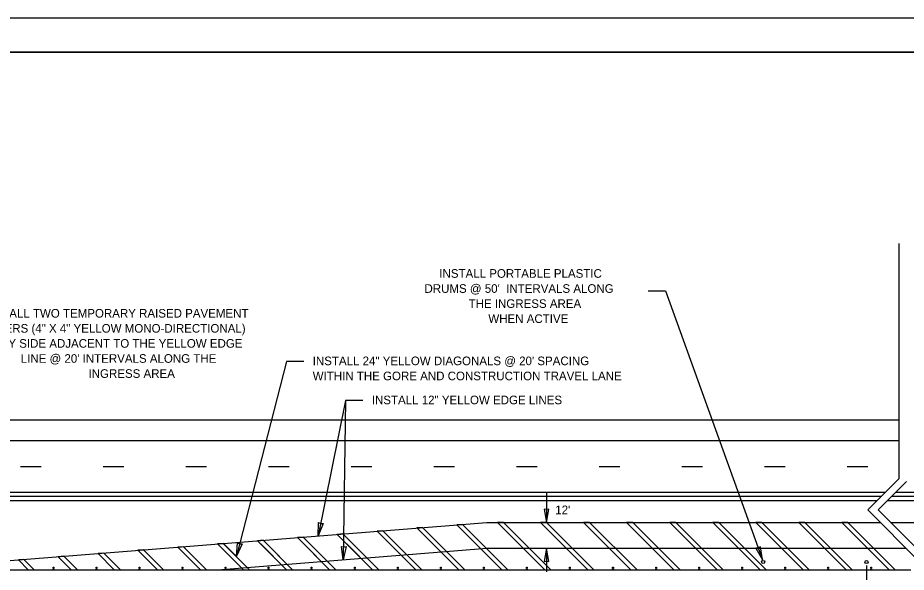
# Model space of a CAD drawing. Extents: x -2541 to -1265, y -5743 to -4928.
# Drawn here: x -2108.9 to -1696.1, y -5185.3 to -4927.7 of the extents above; entities that cross this region are included whole.
import ezdxf

# ---------------------------------------------------------------- set-up
doc = ezdxf.new("R2010")
doc.units = 0
for name, color, linetype in [('Level 42', 7, 'Continuous'), ('Level 45', 7, 'Continuous'), ('Level 46', 7, 'Continuous'), ('Level 48', 7, 'Continuous'), ('Level 49', 7, 'Continuous'), ('Level 50', 7, 'Continuous'), ('TR_WZ_TC_Edge Lines', 7, 'Continuous')]:
    doc.layers.add(name, color=color, linetype=linetype)

msp = doc.modelspace()

# ---------------------------------------------------------------- linework, layer by layer
at = {"layer": 'Level 42'}
for p, q in [((-1278.76, -4943.69), (-2472.96, -4943.66)), ((-1863.17, -5147.99), (-1863.17, -5162.16)), ((-1863.17, -5174.16), (-1863.17, -5185.16))]:
    msp.add_line(p, q, dxfattribs=at)
msp.add_lwpolyline([(-2472.96, -4943.66), (-1412.92, -4943.66), (-1412.92, -5724.9), (-2472.96, -5724.9)], close=True, dxfattribs=at)
at = {"layer": 'Level 45'}
for p, q in [((-2451.65, -5148.16), (-1705.85, -5148.16)), ((-1701.04, -5148.16), (-1460.65, -5148.16)), ((-2451.65, -5184.16), (-1693.96, -5184.16)), ((-2092.51, -5183.2), (-2092.51, -5182.88)), ((-2092.51, -5182.88), (-2092.19, -5182.88)), ((-2092.19, -5183.2), (-2092.51, -5183.2)), ((-2092.51, -5183.84), (-2092.51, -5183.52)), ((-2092.51, -5183.52), (-2092.19, -5183.52)), ((-2092.19, -5183.84), (-2092.51, -5183.84)), ((-2092.19, -5182.88), (-2092.19, -5183.2)), ((-2092.19, -5183.52), (-2092.19, -5183.84)), ((-2072.51, -5183.2), (-2072.51, -5182.88)), ((-2072.51, -5182.88), (-2072.19, -5182.88)), ((-2072.19, -5183.2), (-2072.51, -5183.2)), ((-2072.51, -5183.84), (-2072.51, -5183.52)), ((-2072.51, -5183.52), (-2072.19, -5183.52)), ((-2072.19, -5183.84), (-2072.51, -5183.84)), ((-2072.19, -5182.88), (-2072.19, -5183.2)), ((-2072.19, -5183.52), (-2072.19, -5183.84)), ((-2052.51, -5183.2), (-2052.51, -5182.88)), ((-2052.51, -5182.88), (-2052.19, -5182.88)), ((-2052.19, -5183.2), (-2052.51, -5183.2)), ((-2052.51, -5183.84), (-2052.51, -5183.52)), ((-2052.51, -5183.52), (-2052.19, -5183.52)), ((-2052.19, -5183.84), (-2052.51, -5183.84)), ((-2052.19, -5182.88), (-2052.19, -5183.2)), ((-2052.19, -5183.52), (-2052.19, -5183.84)), ((-2032.51, -5183.2), (-2032.51, -5182.88)), ((-2032.51, -5182.88), (-2032.19, -5182.88)), ((-2032.19, -5183.2), (-2032.51, -5183.2)), ((-2032.51, -5183.84), (-2032.51, -5183.52)), ((-2032.51, -5183.52), (-2032.19, -5183.52)), ((-2032.19, -5183.84), (-2032.51, -5183.84)), ((-2032.19, -5182.88), (-2032.19, -5183.2)), ((-2032.19, -5183.52), (-2032.19, -5183.84)), ((-2012.51, -5183.2), (-2012.51, -5182.88)), ((-2012.51, -5182.88), (-2012.19, -5182.88)), ((-2012.19, -5183.2), (-2012.51, -5183.2)), ((-2012.51, -5183.84), (-2012.51, -5183.52)), ((-2012.51, -5183.52), (-2012.19, -5183.52)), ((-2012.19, -5183.84), (-2012.51, -5183.84)), ((-2012.19, -5182.88), (-2012.19, -5183.2)), ((-2012.19, -5183.52), (-2012.19, -5183.84)), ((-1992.51, -5183.2), (-1992.51, -5182.88)), ((-1992.51, -5182.88), (-1992.19, -5182.88)), ((-1992.19, -5183.2), (-1992.51, -5183.2)), ((-1992.51, -5183.84), (-1992.51, -5183.52)), ((-1992.51, -5183.52), (-1992.19, -5183.52)), ((-1992.19, -5183.84), (-1992.51, -5183.84)), ((-1992.19, -5182.88), (-1992.19, -5183.2)), ((-1992.19, -5183.52), (-1992.19, -5183.84)), ((-1972.51, -5183.2), (-1972.51, -5182.88)), ((-1972.51, -5182.88), (-1972.19, -5182.88)), ((-1972.19, -5183.2), (-1972.51, -5183.2)), ((-1972.51, -5183.84), (-1972.51, -5183.52)), ((-1972.51, -5183.52), (-1972.19, -5183.52)), ((-1972.19, -5183.84), (-1972.51, -5183.84)), ((-1972.19, -5182.88), (-1972.19, -5183.2)), ((-1972.19, -5183.52), (-1972.19, -5183.84)), ((-1952.51, -5183.2), (-1952.51, -5182.88)), ((-1952.51, -5182.88), (-1952.19, -5182.88)), ((-1952.19, -5183.2), (-1952.51, -5183.2)), ((-1952.51, -5183.84), (-1952.51, -5183.52)), ((-1952.51, -5183.52), (-1952.19, -5183.52)), ((-1952.19, -5183.84), (-1952.51, -5183.84)), ((-1952.19, -5182.88), (-1952.19, -5183.2)), ((-1952.19, -5183.52), (-1952.19, -5183.84)), ((-1932.51, -5183.2), (-1932.51, -5182.88)), ((-1932.51, -5182.88), (-1932.19, -5182.88)), ((-1932.19, -5183.2), (-1932.51, -5183.2)), ((-1932.51, -5183.84), (-1932.51, -5183.52)), ((-1932.51, -5183.52), (-1932.19, -5183.52)), ((-1932.19, -5183.84), (-1932.51, -5183.84)), ((-1932.19, -5182.88), (-1932.19, -5183.2)), ((-1932.19, -5183.52), (-1932.19, -5183.84)), ((-1912.51, -5183.2), (-1912.51, -5182.88)), ((-1912.51, -5182.88), (-1912.19, -5182.88)), ((-1912.19, -5183.2), (-1912.51, -5183.2)), ((-1912.51, -5183.84), (-1912.51, -5183.52)), ((-1912.51, -5183.52), (-1912.19, -5183.52)), ((-1912.19, -5183.84), (-1912.51, -5183.84)), ((-1912.19, -5182.88), (-1912.19, -5183.2)), ((-1912.19, -5183.52), (-1912.19, -5183.84)), ((-1892.51, -5183.2), (-1892.51, -5182.88)), ((-1892.51, -5182.88), (-1892.19, -5182.88)), ((-1892.19, -5183.2), (-1892.51, -5183.2)), ((-1892.51, -5183.84), (-1892.51, -5183.52)), ((-1892.51, -5183.52), (-1892.19, -5183.52)), ((-1892.19, -5183.84), (-1892.51, -5183.84)), ((-1892.19, -5182.88), (-1892.19, -5183.2)), ((-1892.19, -5183.52), (-1892.19, -5183.84)), ((-1872.51, -5183.2), (-1872.51, -5182.88)), ((-1872.51, -5182.88), (-1872.19, -5182.88)), ((-1872.19, -5183.2), (-1872.51, -5183.2)), ((-1872.51, -5183.84), (-1872.51, -5183.52)), ((-1872.51, -5183.52), (-1872.19, -5183.52)), ((-1872.19, -5183.84), (-1872.51, -5183.84)), ((-1872.19, -5182.88), (-1872.19, -5183.2)), ((-1872.19, -5183.52), (-1872.19, -5183.84)), ((-1852.51, -5183.2), (-1852.51, -5182.88)), ((-1852.51, -5182.88), (-1852.19, -5182.88)), ((-1852.19, -5183.2), (-1852.51, -5183.2)), ((-1852.51, -5183.84), (-1852.51, -5183.52)), ((-1852.51, -5183.52), (-1852.19, -5183.52)), ((-1852.19, -5183.84), (-1852.51, -5183.84)), ((-1852.19, -5182.88), (-1852.19, -5183.2)), ((-1852.19, -5183.52), (-1852.19, -5183.84)), ((-1832.51, -5183.2), (-1832.51, -5182.88)), ((-1832.51, -5182.88), (-1832.19, -5182.88)), ((-1832.19, -5183.2), (-1832.51, -5183.2)), ((-1832.51, -5183.84), (-1832.51, -5183.52)), ((-1832.51, -5183.52), (-1832.19, -5183.52)), ((-1832.19, -5183.84), (-1832.51, -5183.84)), ((-1832.19, -5182.88), (-1832.19, -5183.2)), ((-1832.19, -5183.52), (-1832.19, -5183.84)), ((-1812.51, -5183.2), (-1812.51, -5182.88)), ((-1812.51, -5182.88), (-1812.19, -5182.88)), ((-1812.19, -5183.2), (-1812.51, -5183.2)), ((-1812.51, -5183.84), (-1812.51, -5183.52)), ((-1812.51, -5183.52), (-1812.19, -5183.52)), ((-1812.19, -5183.84), (-1812.51, -5183.84)), ((-1812.19, -5182.88), (-1812.19, -5183.2)), ((-1812.19, -5183.52), (-1812.19, -5183.84)), ((-1792.51, -5183.2), (-1792.51, -5182.88)), ((-1792.51, -5182.88), (-1792.19, -5182.88)), ((-1792.19, -5183.2), (-1792.51, -5183.2)), ((-1792.51, -5183.84), (-1792.51, -5183.52)), ((-1792.51, -5183.52), (-1792.19, -5183.52)), ((-1792.19, -5183.84), (-1792.51, -5183.84)), ((-1792.19, -5182.88), (-1792.19, -5183.2)), ((-1792.19, -5183.52), (-1792.19, -5183.84)), ((-1772.51, -5183.2), (-1772.51, -5182.88)), ((-1772.51, -5182.88), (-1772.19, -5182.88)), ((-1772.19, -5183.2), (-1772.51, -5183.2)), ((-1772.51, -5183.84), (-1772.51, -5183.52)), ((-1772.51, -5183.52), (-1772.19, -5183.52)), ((-1772.19, -5183.84), (-1772.51, -5183.84)), ((-1772.19, -5182.88), (-1772.19, -5183.2)), ((-1772.19, -5183.52), (-1772.19, -5183.84)), ((-1752.51, -5183.2), (-1752.51, -5182.88)), ((-1752.51, -5182.88), (-1752.19, -5182.88)), ((-1752.19, -5183.2), (-1752.51, -5183.2)), ((-1752.51, -5183.84), (-1752.51, -5183.52)), ((-1752.51, -5183.52), (-1752.19, -5183.52)), ((-1752.19, -5183.84), (-1752.51, -5183.84)), ((-1752.19, -5182.88), (-1752.19, -5183.2)), ((-1752.19, -5183.52), (-1752.19, -5183.84)), ((-1732.51, -5183.2), (-1732.51, -5182.88)), ((-1732.51, -5182.88), (-1732.19, -5182.88)), ((-1732.19, -5183.2), (-1732.51, -5183.2)), ((-1732.51, -5183.84), (-1732.51, -5183.52)), ((-1732.51, -5183.52), (-1732.19, -5183.52)), ((-1732.19, -5183.84), (-1732.51, -5183.84)), ((-1732.19, -5182.88), (-1732.19, -5183.2)), ((-1732.19, -5183.52), (-1732.19, -5183.84)), ((-1712.51, -5183.2), (-1712.51, -5182.88)), ((-1712.51, -5182.88), (-1712.19, -5182.88)), ((-1712.19, -5183.2), (-1712.51, -5183.2)), ((-1712.51, -5183.84), (-1712.51, -5183.52)), ((-1712.51, -5183.52), (-1712.19, -5183.52)), ((-1712.19, -5183.84), (-1712.51, -5183.84)), ((-1712.19, -5182.88), (-1712.19, -5183.2)), ((-1712.19, -5183.52), (-1712.19, -5183.84))]:
    msp.add_line(p, q, dxfattribs=at)
at = {"layer": 'Level 46'}
for p, q in [((-1815.99, -5054.56), (-1807.99, -5054.56)), ((-1807.99, -5054.56), (-1762.82, -5179.6)), ((-1984.02, -5087.36), (-2007.28, -5177.84)), ((-1976.02, -5087.36), (-1984.02, -5087.36)), ((-1956.55, -5105.52), (-1969.32, -5168.42)), ((-1956.55, -5105.52), (-1957.66, -5179.49)), ((-1948.55, -5105.52), (-1956.55, -5105.52)), ((-2451.65, -5114.56), (-1699.44, -5114.56)), ((-2451.65, -5124.16), (-1699.44, -5124.16)), ((-2107.6, -5136.16), (-2098, -5136.16)), ((-2069.2, -5136.16), (-2059.6, -5136.16)), ((-2030.8, -5136.16), (-2021.2, -5136.16)), ((-1992.4, -5136.16), (-1982.8, -5136.16)), ((-1954, -5136.16), (-1944.4, -5136.16)), ((-1915.6, -5136.16), (-1906, -5136.16)), ((-1877.2, -5136.16), (-1867.6, -5136.16)), ((-1838.8, -5136.16), (-1829.2, -5136.16)), ((-1800.4, -5136.16), (-1790.8, -5136.16)), ((-1762, -5136.16), (-1752.4, -5136.16)), ((-1723.6, -5136.16), (-1714, -5136.16)), ((-1714.59, -5182.24), (-1714.59, -5261.76))]:
    msp.add_line(p, q, dxfattribs=at)
at = {"layer": 'Level 48'}
for p, q in [((-1707.77, -5150.08), (-2166, -5150.08)), ((-1707.77, -5150.08), (-1709.69, -5152)), ((-1702.96, -5150.08), (-1704.88, -5152)), ((-1460.65, -5150.08), (-1702.96, -5150.08)), ((-2166, -5152), (-1709.69, -5152)), ((-1704.88, -5152), (-1460.65, -5152))]:
    msp.add_line(p, q, dxfattribs=at)
at = {"layer": 'Level 49'}
for p, q in [((-1863.17, -5156.2), (-1864.25, -5156.01)), ((-1864.25, -5156.01), (-1863.17, -5162.16)), ((-1863.17, -5162.16), (-1862.09, -5156.01)), ((-1862.09, -5156.01), (-1863.17, -5156.2)), ((-1969.32, -5168.42), (-1969.16, -5162.18)), ((-1967.04, -5162.61), (-1969.32, -5168.42)), ((-1969.16, -5162.18), (-1968.14, -5162.59)), ((-1968.14, -5162.59), (-1967.04, -5162.61)), ((-2007.28, -5177.84), (-2006.8, -5171.62)), ((-2006.8, -5171.62), (-2005.79, -5172.07)), ((-2004.7, -5172.16), (-2007.28, -5177.84)), ((-2005.79, -5172.07), (-2004.7, -5172.16)), ((-1957.66, -5179.49), (-1958.5, -5173.3)), ((-1958.5, -5173.3), (-1957.42, -5173.54)), ((-1956.33, -5173.39), (-1957.66, -5179.49)), ((-1957.42, -5173.54), (-1956.33, -5173.39)), ((-1863.17, -5174.16), (-1864.25, -5180.3)), ((-1862.09, -5180.3), (-1863.17, -5174.16)), ((-1764.84, -5174), (-1765.92, -5174.19)), ((-1765.92, -5174.19), (-1762.82, -5179.6)), ((-1763.89, -5173.45), (-1764.84, -5174)), ((-1762.82, -5179.6), (-1763.89, -5173.45)), ((-1864.25, -5180.3), (-1863.17, -5180.11)), ((-1863.17, -5180.11), (-1862.09, -5180.3))]:
    msp.add_line(p, q, dxfattribs=at)
at = {"layer": 'Level 50'}
for p, q in [((-1699.44, -5141.74), (-1699.44, -5032.65)), ((-1714.02, -5156.33), (-1699.44, -5141.74)), ((-1709.22, -5156.33), (-1696.04, -5143.15)), ((-1690.08, -5180.27), (-1714.02, -5156.33)), ((-1685.27, -5180.27), (-1709.22, -5156.33))]:
    msp.add_line(p, q, dxfattribs=at)
msp.add_lwpolyline([(-2541.13, -4927.7), (-1265.77, -4927.7), (-1265.77, -5742.8), (-2541.13, -5742.8)], close=True, dxfattribs=at)
for centre in [(-1762.58, -5180.55), (-1714.59, -5180.56)]:
    msp.add_circle(centre, 0.72, dxfattribs=at)
at = {"layer": 'TR_WZ_TC_Edge Lines'}
for p, q in [((-2166, -5184.16), (-1891, -5162.16)), ((-1902.29, -5163.06), (-1904.91, -5163.27)), ((-1904.91, -5163.27), (-1884.02, -5184.16)), ((-1881.19, -5184.16), (-1902.29, -5163.06)), ((-1891, -5162.16), (-1708.2, -5162.16)), ((-1883.19, -5162.16), (-1886.02, -5162.16)), ((-1886.02, -5162.16), (-1864.02, -5184.16)), ((-1861.19, -5184.16), (-1883.19, -5162.16)), ((-1863.19, -5162.16), (-1866.02, -5162.16)), ((-1866.02, -5162.16), (-1844.02, -5184.16)), ((-1841.19, -5184.16), (-1863.19, -5162.16)), ((-1843.19, -5162.16), (-1846.02, -5162.16)), ((-1846.02, -5162.16), (-1824.02, -5184.16)), ((-1821.19, -5184.16), (-1843.19, -5162.16)), ((-1823.19, -5162.16), (-1826.02, -5162.16)), ((-1826.02, -5162.16), (-1804.02, -5184.16)), ((-1801.19, -5184.16), (-1823.19, -5162.16)), ((-1803.19, -5162.16), (-1806.02, -5162.16)), ((-1806.02, -5162.16), (-1784.02, -5184.16)), ((-1781.19, -5184.16), (-1803.19, -5162.16)), ((-1783.19, -5162.16), (-1786.02, -5162.16)), ((-1786.02, -5162.16), (-1764.02, -5184.16)), ((-1761.19, -5184.16), (-1783.19, -5162.16)), ((-1763.19, -5162.16), (-1766.02, -5162.16)), ((-1766.02, -5162.16), (-1744.02, -5184.16)), ((-1741.19, -5184.16), (-1763.19, -5162.16)), ((-1743.19, -5162.16), (-1746.02, -5162.16)), ((-1746.02, -5162.16), (-1724.02, -5184.16)), ((-1721.19, -5184.16), (-1743.19, -5162.16)), ((-1723.19, -5162.16), (-1726.02, -5162.16)), ((-1726.02, -5162.16), (-1704.02, -5184.16)), ((-1701.19, -5184.16), (-1723.19, -5162.16)), ((-1703.39, -5162.16), (-1511.03, -5162.16)), ((-1957.84, -5167.5), (-1960.46, -5167.71)), ((-1960.46, -5167.71), (-1944.02, -5184.16)), ((-1941.19, -5184.16), (-1957.84, -5167.5)), ((-1939.33, -5166.02), (-1941.94, -5166.23)), ((-1941.94, -5166.23), (-1924.02, -5184.16)), ((-1921.19, -5184.16), (-1939.33, -5166.02)), ((-1920.81, -5164.54), (-1923.43, -5164.75)), ((-1923.43, -5164.75), (-1904.02, -5184.16)), ((-1901.19, -5184.16), (-1920.81, -5164.54)), ((-1994.88, -5170.47), (-1997.5, -5170.68)), ((-1997.5, -5170.68), (-1984.02, -5184.16)), ((-1981.19, -5184.16), (-1994.88, -5170.47)), ((-1976.36, -5168.98), (-1978.98, -5169.19)), ((-1978.98, -5169.19), (-1964.02, -5184.16)), ((-1961.19, -5184.16), (-1976.36, -5168.98)), ((-2050.44, -5174.91), (-2053.06, -5175.12)), ((-2044.02, -5184.16), (-2053.06, -5175.12)), ((-2053.06, -5175.12), (-2044.02, -5184.16)), ((-2041.19, -5184.16), (-2050.44, -5174.91)), ((-2041.19, -5184.16), (-2050.44, -5174.91)), ((-2031.92, -5173.43), (-2034.54, -5173.64)), ((-2024.02, -5184.16), (-2034.54, -5173.64)), ((-2034.54, -5173.64), (-2024.02, -5184.16)), ((-2021.19, -5184.16), (-2031.92, -5173.43)), ((-2021.19, -5184.16), (-2031.92, -5173.43)), ((-2013.4, -5171.95), (-2016.02, -5172.16)), ((-2004.02, -5184.16), (-2016.02, -5172.16)), ((-2016.02, -5172.16), (-2004.02, -5184.16)), ((-2016, -5184.16), (-1891, -5174.16)), ((-2001.19, -5184.16), (-2013.4, -5171.95)), ((-2001.19, -5184.16), (-2013.19, -5172.16)), ((-1984.02, -5184.16), (-1996.02, -5172.16)), ((-1981.19, -5184.16), (-1993.19, -5172.16)), ((-1964.02, -5184.16), (-1976.02, -5172.16)), ((-1944.02, -5184.16), (-1956.02, -5172.16)), ((-1924.02, -5184.16), (-1936.02, -5172.16)), ((-1891, -5174.16), (-1696.2, -5174.16)), ((-2105.99, -5179.35), (-2108.61, -5179.56)), ((-2104.02, -5184.16), (-2108.61, -5179.56)), ((-2108.61, -5179.56), (-2104.02, -5184.16)), ((-2101.19, -5184.16), (-2105.99, -5179.35)), ((-2101.19, -5184.16), (-2105.99, -5179.35)), ((-2087.47, -5177.87), (-2090.09, -5178.08)), ((-2084.02, -5184.16), (-2090.09, -5178.08)), ((-2090.09, -5178.08), (-2084.02, -5184.16)), ((-2081.19, -5184.16), (-2087.47, -5177.87)), ((-2081.19, -5184.16), (-2087.47, -5177.87)), ((-2068.96, -5176.39), (-2071.57, -5176.6)), ((-2064.02, -5184.16), (-2071.57, -5176.6)), ((-2071.57, -5176.6), (-2064.02, -5184.16)), ((-2061.19, -5184.16), (-2068.96, -5176.39)), ((-2061.19, -5184.16), (-2068.96, -5176.39)), ((-2104.02, -5184.16), (-2101.19, -5184.16)), ((-2084.02, -5184.16), (-2081.19, -5184.16)), ((-2064.02, -5184.16), (-2061.19, -5184.16)), ((-2044.02, -5184.16), (-2041.19, -5184.16)), ((-2024.02, -5184.16), (-2021.19, -5184.16)), ((-2004.02, -5184.16), (-2001.19, -5184.16)), ((-1984.02, -5184.16), (-1981.19, -5184.16)), ((-1964.02, -5184.16), (-1961.19, -5184.16)), ((-1944.02, -5184.16), (-1941.19, -5184.16)), ((-1924.02, -5184.16), (-1921.19, -5184.16)), ((-1904.02, -5184.16), (-1901.19, -5184.16)), ((-1884.02, -5184.16), (-1881.19, -5184.16)), ((-1864.02, -5184.16), (-1861.19, -5184.16)), ((-1844.02, -5184.16), (-1841.19, -5184.16)), ((-1824.02, -5184.16), (-1821.19, -5184.16)), ((-1804.02, -5184.16), (-1801.19, -5184.16)), ((-1784.02, -5184.16), (-1781.19, -5184.16)), ((-1764.02, -5184.16), (-1761.19, -5184.16)), ((-1744.02, -5184.16), (-1741.19, -5184.16)), ((-1724.02, -5184.16), (-1721.19, -5184.16)), ((-1704.02, -5184.16), (-1701.19, -5184.16))]:
    msp.add_line(p, q, dxfattribs=at)

# ---------------------------------------------------------------- texts
at = {"layer": 'Level 42'}
for s, p in [('INSTALL PORTABLE PLASTIC', (-1913.03, -5048.5)), ("DRUMS @ 50'  INTERVALS ALONG", (-1919.93, -5055.5)), ('THE INGRESS AREA', (-1899.44, -5062.5)), ('INSTALL TWO TEMPORARY RAISED PAVEMENT', (-2125.03, -5067)), ('WHEN ACTIVE', (-1890.26, -5069.5)), ('MARKERS (4" X 4" YELLOW MONO-DIRECTIONAL)', (-2130.46, -5074)), ('SIDE BY SIDE ADJACENT TO THE YELLOW EDGE', (-2130.8, -5081)), ("LINE @ 20' INTERVALS ALONG THE", (-2107.49, -5088)), ('INSTALL 24" YELLOW DIAGONALS @ 20\' SPACING', (-1971.86, -5089.11)), ('INGRESS AREA', (-2076.01, -5095)), ('WITHIN THE GORE AND CONSTRUCTION TRAVEL LANE', (-1971.86, -5096.11)), ('INSTALL 12" YELLOW EDGE LINES', (-1944.39, -5107.27)), ("12'", (-1859.17, -5158.34))]:
    msp.add_text(s, height=4, dxfattribs=at).set_placement(p)

doc.saveas('drawing.dxf')
